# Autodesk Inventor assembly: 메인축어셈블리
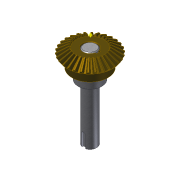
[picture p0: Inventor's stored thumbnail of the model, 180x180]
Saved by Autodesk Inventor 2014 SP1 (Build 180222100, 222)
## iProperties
Created: 2014-10
Part Number: 메인축어셈블리
Document SubType Name: Assembly
Designer: KYOUNG IL JANG
Author: KYOUNG IL JANG
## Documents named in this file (5)
- D:\20_MDU\10_기술자격시험\20_Inventor\2014-10월 출제중\2급\메인축어셈블리.iam
- D:\20_MDU\10_기술자격시험\20_Inventor\2014-10월 출제중\2급\메인 베벨기어.ipt
- D:\20_MDU\10_기술자격시험\20_Inventor\2014-10월 출제중\2급\메인 축.ipt
- 메인 축.ipt
- D:\20_MDU\10_기술자격시험\20_Inventor\2014-10월 출제중\2급\키 5x5.ipt
